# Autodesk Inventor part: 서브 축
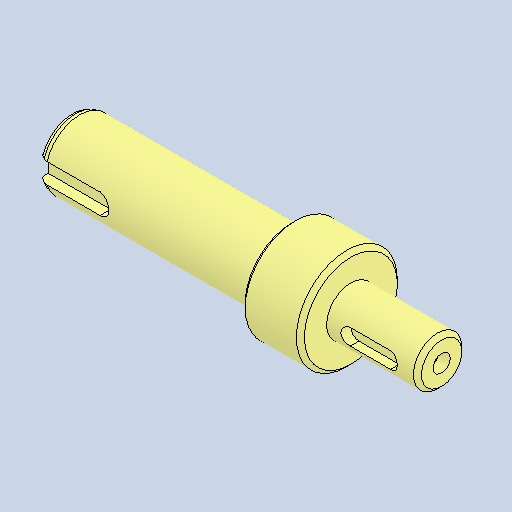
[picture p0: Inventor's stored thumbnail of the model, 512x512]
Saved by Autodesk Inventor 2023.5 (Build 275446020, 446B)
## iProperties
Created: 2026-07
Part Number: 서브 축
Material: 강철, 탄소
Document SubType Name: Modeling
Designer: mirae
Density: 7.85 g/cm^3
Appearance: 기본값
Author: jhkim
Revision Number: 1
Sending System: Autodesk Inventor 2027
Preprocessor: ST-DEVELOPER v20.1
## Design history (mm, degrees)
node "서브 축1"
node "솔리드2"
node "솔리드1"
